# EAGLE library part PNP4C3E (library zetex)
PNP TRANSISTOR
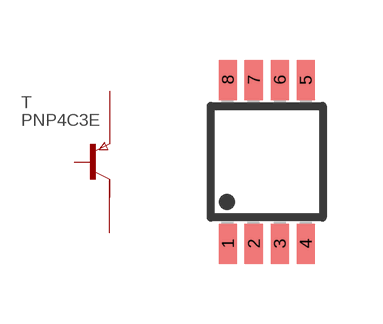
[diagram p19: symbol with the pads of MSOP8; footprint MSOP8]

Designator prefix T

## PNP4C3E (OC_FARNELL: unknown; OC_NEWARK: unknown)  [MSOP8]
1  E  pas
2  E1  pas
3  E2  pas
4  B  pas
5  C  pas
6  C1  pas
7  C2  pas
8  C3  pas

## Footprint MSOP8 (pad centres in mm)
Micro Small Outline Package
smd 0.45 x 1: 1 -0.975,-2.05; 2 -0.325,-2.05; 3 0.325,-2.05; 4 0.975,-2.05; 5 0.975,2.05; 6 0.325,2.05; 7 -0.325,2.05; 8 -0.975,2.05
